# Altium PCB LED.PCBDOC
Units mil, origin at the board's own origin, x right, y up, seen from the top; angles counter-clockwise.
Board outline 6000 x 4000 mil, 2 copper layers (Top Layer, Bottom Layer); 19 components, 28 nets, 110 pads, 17 vias.
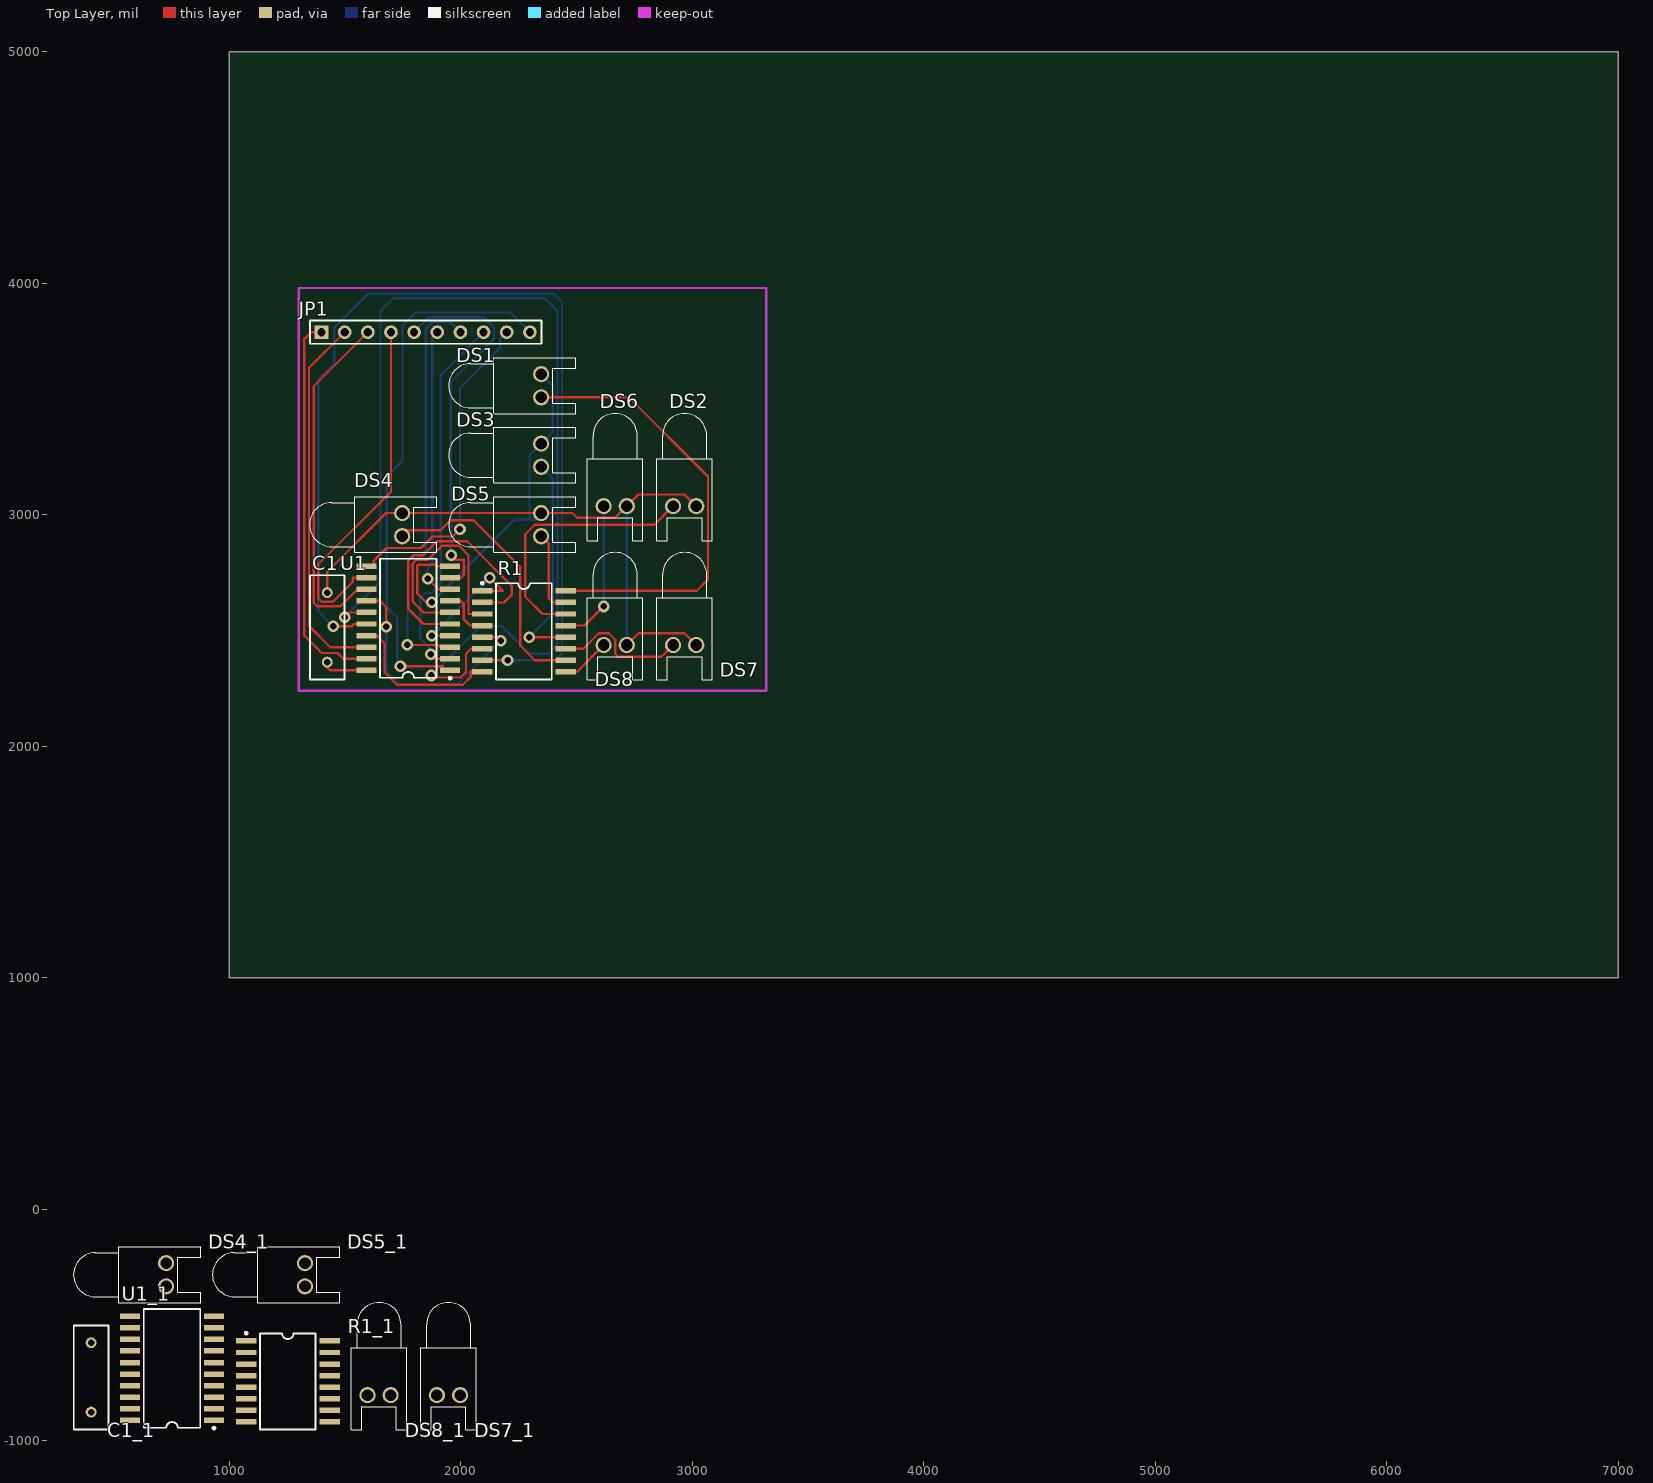
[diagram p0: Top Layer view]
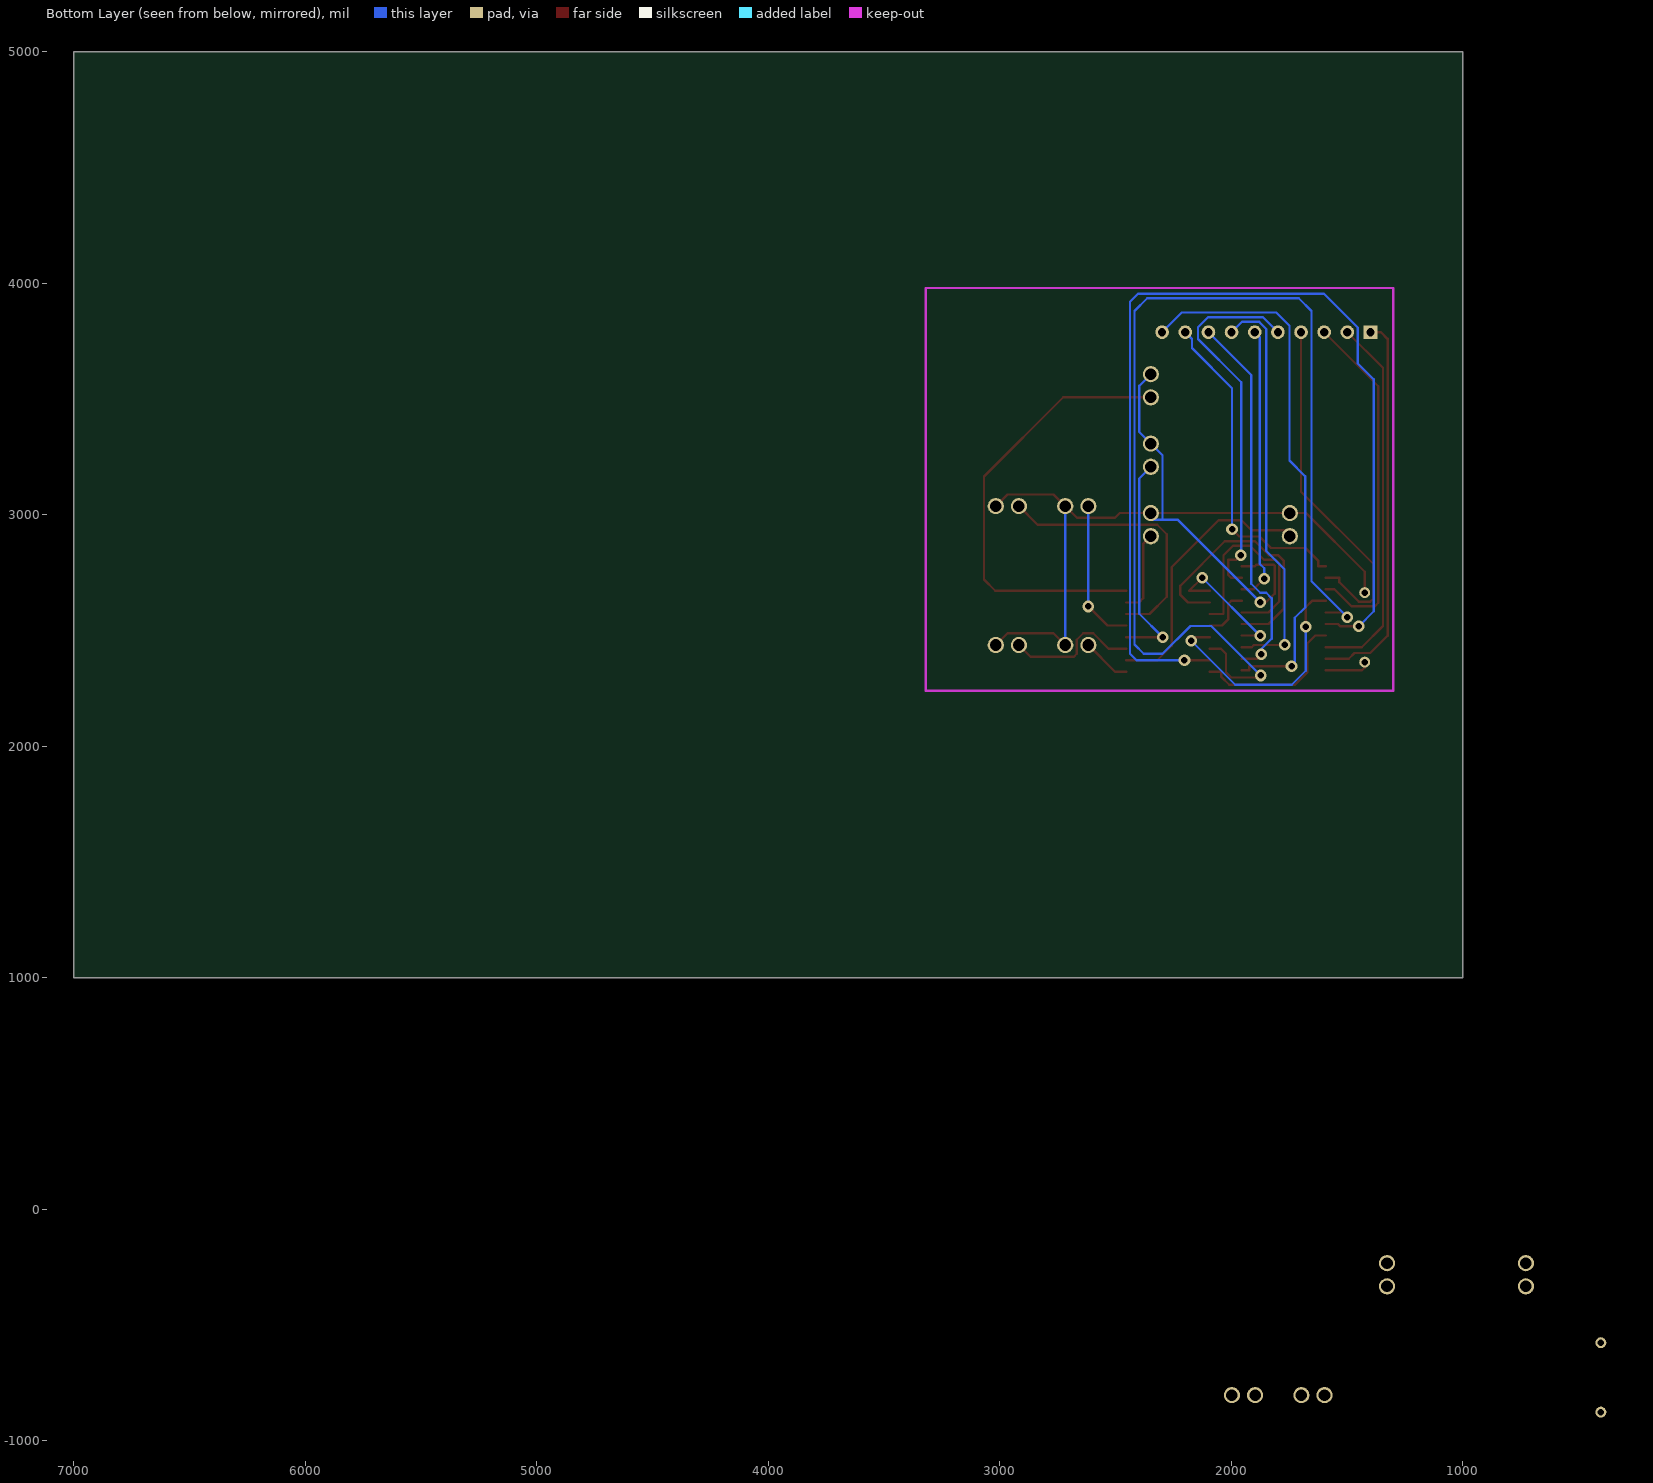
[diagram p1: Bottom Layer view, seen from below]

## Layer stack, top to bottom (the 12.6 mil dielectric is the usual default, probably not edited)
Top Layer: signal copper 1.4
Dielectric: dielectric 12.6, FR-4, Dk 4.8
Bottom Layer: signal copper 1.4

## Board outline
1000,1000 7000,1000 7000,5000 1000,5000

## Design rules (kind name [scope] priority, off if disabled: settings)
Clearance [All] p1: gap=10
ComponentClearance [All] p1: gap=10 collisioncheckmode=0
PolygonConnect [All] p1: connectstyle=Relief reliefconductorwidth=10 reliefentries=4 polygonreliefangle="90 Angle"
RoomDefinition LED [InComponentClass('LED')] p1: confinementstyle=ConfineIn formatcopy=TRUE outline 1320,2280 3220,2280 3220,3900 1320,3900
RoutingLayers [All] p1: top layer=Horizontal bottom layer=Vertical
RoutingVias [All] p1: holewidth=28 width=50 viastyle="Through Hole" minholewidth=28 minwidth=50 maxholewidth=28 maxwidth=50
SolderMaskExpansion [All] p1: expansion=4
TestPointUsage [All] p1: valid=0 allowmultiple=FALSE
Testpoint [All] p1: side=15 testpointundercomponent=TRUE minsize=40 maxsize=100 preferedsize=60 minholesize=0 maxholesize=40 preferedholesize=32 testpointgrid=1 style=1023 order=-539222988
Width [All] p1: maxlimit=10 minlimit=10 preferedwidth=10
16 further rules are at their usual default settings.

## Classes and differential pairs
component class LED: C1 DS1 DS2 DS3 DS4 DS5 DS6 DS7 DS8 JP1 R1 U1

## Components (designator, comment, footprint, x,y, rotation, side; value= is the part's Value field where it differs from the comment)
C1 "0.1uF" RAD-0.3 1423.94,2663.94 r270 top
C1_1 "0.1uF" RAD-0.3 403.94,-576.06 r270 top (schematic designator C1)
DS1 "LED0" LED-0 2347.5,3557.5 r270 top
DS2 "LED0" LED-0 2967.5,3037.5 r180 top
DS3 "LED0" LED-0 2347.5,3257.5 r270 top
DS4 "LED0" LED-0 1747.5,2957.5 r270 top
DS4_1 "LED0" LED-0 727.5,-282.5 r270 top (schematic designator DS4)
DS5 "LED0" LED-0 2347.5,2957.5 r270 top
DS5_1 "LED0" LED-0 1327.5,-282.5 r270 top (schematic designator DS5)
DS6 "LED0" LED-0 2667.5,3037.5 r180 top
DS7 "LED0" LED-0 2967.5,2437.5 r180 top
DS7_1 "LED0" LED-0 1947.5,-802.5 r180 top (schematic designator DS7)
DS8 "LED0" LED-0 2667.5,2437.5 r180 top
DS8_1 "LED0" LED-0 1647.5,-802.5 r180 top (schematic designator DS8)
JP1 "Header 10" HDR1X10 1398.94,3788.94 r0 top
R1 "330" SO-G16/G6.9 2273.41,2496.61 r270 top
R1_1 "330" SO-G16/G6.9 1253.41,-743.39 r270 top (schematic designator R1)
U1 "TPIC6B273DW" SO-G20 1773.41,2553.31 r90 top
U1_1 "TPIC6B273DW" SO-G20 753.41,-686.69 r90 top (schematic designator U1)

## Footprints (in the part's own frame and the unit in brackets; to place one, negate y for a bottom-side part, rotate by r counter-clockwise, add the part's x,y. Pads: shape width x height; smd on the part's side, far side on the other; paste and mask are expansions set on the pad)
HDR1X10 [mm]
  rect 1.5x1.5 hole 0.9: 1(0,0)
  round 1.5 hole 0.9: 2(2.54,0) 3(5.08,0) 4(7.62,0) 5(10.16,0) 6(12.7,0) 7(15.24,0) 8(17.78,0) 9(20.32,0) 10(22.86,0)
  silkscreen extent -1.27,-1.27 24.13,1.27
LED-0 [mil]
  round 70 hole 50: 1(50,0) 2(-50,0)
  silkscreen extent -120,-400 120,150
RAD-0.3 [mm]
  round 1.2 hole 0.7: 1(0,0) 2(7.62,0)
  silkscreen extent -1.91,-1.9 9.52,1.91
SO-G16/G6.9 [mm]
  rect 0.6x2.25 smd: 1(-4.445,-4.575) 2(-3.175,-4.575) 3(-1.905,-4.575) 4(-0.635,-4.575) 5(0.635,-4.575) 6(1.905,-4.575) 7(3.175,-4.575) 8(4.445,-4.575) 9(4.445,4.575) 10(3.175,4.575) 11(1.905,4.575) 12(0.635,4.575) 13(-0.635,4.575) 14(-1.905,4.575) 15(-3.175,4.575) 16(-4.445,4.575)
  silkscreen extent -5.42,-4.7 5.27,3.05
SO-G20 [mm]
  rect 0.6x2.2 smd: 1(-5.715,-4.6) 2(-4.445,-4.6) 3(-3.175,-4.6) 4(-1.905,-4.6) 5(-0.635,-4.6) 6(0.635,-4.6) 7(1.905,-4.6) 8(3.175,-4.6) 9(4.445,-4.6) 10(5.715,-4.6) 11(5.715,4.6) 12(4.445,4.6) 13(3.175,4.6) 14(1.905,4.6) 15(0.635,4.6) 16(-0.635,4.6) 17(-1.905,4.6) 18(-3.175,4.6) 19(-4.445,4.6) 20(-5.715,4.6)
  silkscreen extent -6.69,-4.73 6.53,3.1

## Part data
C1 C1_1: library part Cap, "Capacitor"
DS1 DS2 DS3 DS4 DS4_1 DS5 DS5_1 DS6 DS7 DS7_1 DS8 DS8_1: "Typical INFRARED GaAs LED"
JP1: "Header, 10-Pin"
R1 R1_1: library part "Res Pack3", "Resistor Array"
U1 U1_1: "Power Logic Octal D-Type Latch"

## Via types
v1: diameter 50, hole 28, Top Layer to Bottom Layer, 17 vias

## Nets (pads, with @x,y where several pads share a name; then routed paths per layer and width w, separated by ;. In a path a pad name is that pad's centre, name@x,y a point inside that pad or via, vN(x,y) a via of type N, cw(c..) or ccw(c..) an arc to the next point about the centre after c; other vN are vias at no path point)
GND: C1.1 DS1.2 DS2.2 DS3.2 DS4.2 DS5.2 DS6.2 DS7.2 DS8.2 U1.10 | length 4486.4
  Top Layer w10: C1.1 1423.94,2753.94 1677.5,3007.5 DS4.2 DS5.2 2482,3007.5 2502.5,2987 2667,2987 DS6.2 2768,3088 2967,3088 DS2.2 ; v1(1876,2623) 1849,2623 1813,2659 1813,2780 1817,2784 1892.31,2784 1898,2778.31 U1.10 ; DS8.2 2768,2488 2967,2488 DS7.2
  Bottom Layer w10: v1(1876,2623) 2231,2978 2297,2978 ; DS5.2 2347.5,2978 2297,2978 ; DS1.2 2398,3557 2398,3358 DS3.2 2297,3257 2297,2978 ; DS8.2 DS6.2
NetDS1_1: DS1.1 R1.16 | length 1942.5
  Top Layer w10: DS1.1 2726.5,3507.5 3068,3166 3068,2720 3019.61,2671.61 R1.16
NetDS2_1: DS2.1 R1.14 | length 1164.5
  Top Layer w10: R1.14 2353.39,2571.61 2279,2646 2279,2916.5 2320,2957.5 2837.5,2957.5 DS2.1
NetDS3_1: DS3.1 R1.12 | length 955.2
  Top Layer w10: v1(2297,2471.61) R1.12
  Bottom Layer w10: v1(2297,2471.61) 2398,2572.61 2398,3157 DS3.1
NetDS4_1: DS4.1 R1.10 | length 1199.9
  Top Layer w10: DS4.1 1747.5,2934 1914,2934 1957,2977 2054,2977 2257,2774 2257,2434.61 2320,2371.61 R1.10
NetDS5_1: DS5.1 R1.15 | length 361.5
  Top Layer w10: DS5.1 2381,2874 2381,2640 2399.39,2621.61 R1.15
NetDS6_1: DS6.1 R1.13 | length 631.5
  Top Layer w10: R1.13 2535,2521.61 v1(2617.5,2604.11)
  Bottom Layer w10: v1(2617.5,2604.11) DS6.1
NetDS7_1: DS7.1 R1.11 | length 590
  Top Layer w10: R1.11 2530,2421.61 2596.39,2488 2640,2488 2667.5,2460.5 2667.5,2399.5 2680,2387 2867,2387 DS7.1
NetDS8_1: DS8.1 R1.9 | length 212
  Top Layer w10: R1.9 2501.61,2321.61 DS8.1
NetJP1_1: JP1.1 U1.19 | length 1676.5
  Top Layer w10: JP1.1 1353.94,3788.94 1325,3760 1325,2478 1400,2403 1468.31,2403 1493,2378.31 U1.19
NetJP1_2: JP1.2 U1.18 | length 1618
  Top Layer w10: JP1.2 1345,3635 1345,2520 1436.69,2428.31 U1.18
NetJP1_3: JP1.3 U1.13 | length 1529.7
  Top Layer w10: U1.13 1554,2678.31 1480.69,2605 1380,2605 1365,2620 1365,3555 JP1.3
NetJP1_4: JP1.4 U1.12 | length 1546.4
  Top Layer w10: U1.12 1534,2728.31 1534,2709.32 1449.68,2625 1400,2625 1385,2640 1385,2786.06 1698.94,3100 JP1.4
NetJP1_5: JP1.5 U1.9 | length 1644
  Top Layer w10: U1.9 2001.13,2728.31 2013,2740.18 2013,2806 1979,2806 v1(1959,2826)
  Bottom Layer w10: JP1.5 1864,3854 2100,3854 2144,3810 2144,3760 1957,3573 1957,2828 v1(1959,2826)
NetJP1_6: JP1.6 U1.8 | length 1197.3
  Top Layer w10: v1(1858,2724) 1903.69,2678.31 U1.8
  Bottom Layer w10: v1(1858,2724) 1858,2769 1877,2788 1877,3767 JP1.6
NetJP1_7: JP1.7 U1.3 | length 1767.7
  Top Layer w10: v1(1770,2438) 1902.31,2438 1912,2428.31 U1.3
  Bottom Layer w10: v1(1770,2438) 1770,2765 1849,2844 1849,3803 1880,3834 1953.88,3834 JP1.7
NetJP1_8: JP1.8 U1.2 | length 1630.7
  Top Layer w10: v1(1870,2397) 1888.69,2378.31 U1.2
  Bottom Layer w10: v1(1870,2397) 1870,2421 1826,2465 1826,2640 1849,2663 1875,2663 1914,2702 1914,3604 JP1.8
NetJP1_9: JP1.9 U1.11 | length 1419.3
  Top Layer w10: U1.11 1624,2778.31 1624,2801 1680,2857 1829,2857 1878,2906 1966,2906 v1(1997,2937)
  Bottom Layer w10: v1(1997,2937) 1997,3547 2170,3720 2170,3760 JP1.9
NetJP1_10: JP1.10 U1.1 | length 2364.6
  Top Layer w10: v1(1740,2346) 1923,2346 1923,2328.31 U1.1
  Bottom Layer w10: v1(1740,2346) 1726,2360 1726,2555 1681,2600 1681,3166 1749,3234 1749,3817 1806,3874 2213.88,3874 JP1.10
NetR1_1: R1.1 U1.4 | length 600.9
  Top Layer w10: v1(1876,2478.31) U1.4 ; R1.1 2182.39,2671.61 v1(2125.85,2728.15)
  Bottom Layer w10: v1(1876,2478.31) v1(2125.85,2728.15)
NetR1_2: R1.2 U1.5 | length 1156.2
  Top Layer w10: U1.5 1840,2528.31 1773,2595.31 1773,2800 1799,2826 1838,2826 1898,2886 2028,2886 2220,2694 2220,2654 2187.61,2621.61 R1.2
NetR1_3: R1.3 U1.6 | length 947.8
  Top Layer w10: U1.6 1840,2578.31 1793,2625.31 1793,2790 1809,2806 1859,2806 1919,2866 1993,2866 2034,2825 2034,2571.61 R1.3
NetR1_4: R1.4 U1.7 | length 222
  Top Layer w10: U1.7 2000,2628.31 2014,2614.31 2014,2547.61 2040,2521.61 R1.4
NetR1_5: R1.5 U1.14 | length 1056.3
  Top Layer w10: U1.14 1651,2628.31 1679,2600.31 v1(1679,2516) ; R1.5 2157.39,2471.61 v1(2173,2456)
  Bottom Layer w10: v1(1679,2516) 1679,2326 1739,2266 1983,2266 v1(2173,2456)
NetR1_6: R1.6 U1.15 | length 4759.5
  Top Layer w10: v1(1499,2558.31) 1519,2578.31 U1.15 ; v1(1873,2306) 1882,2297 2000,2297 2023,2320 2023,2400 2044.61,2421.61 R1.6
  Bottom Layer w10: v1(1499,2558.31) 1654,2713.31 1654,3880 1709,3935 2363,3935 2418,3880 2418,2440 2378,2400 2297,2400 2177,2520 2087,2520 v1(1873,2306)
NetR1_7: R1.7 U1.16 | length 4428.5
  Top Layer w10: v1(1450,2518) 1528.69,2518 1539,2528.31 U1.16 ; R1.7 2202,2371.61 v1(2202.39,2372)
  Bottom Layer w10: v1(1450,2518) 1385,2583 1385,3585 1454,3654 1454,3809 1600,3955 2403,3955 2438,3920 2438,2400 2410,2372 v1(2202.39,2372)
NetR1_8: R1.8 U1.17 | length 697.8
  Top Layer w10: U1.17 1637.69,2478.31 1671,2445 1671,2320 1725,2266 2009,2266 2043,2300 2043,2321.61 R1.8
VCC: C1.2 U1.20 | length 197.2
  Top Layer w10: C1.2 1423.94,2340 1435.63,2328.31 U1.20
pads on no net: C1_1.1 C1_1.2 DS4_1.1 DS4_1.2 DS5_1.1 DS5_1.2 DS7_1.1 DS7_1.2 DS8_1.1 DS8_1.2 R1_1.1 R1_1.2 R1_1.3 R1_1.4 R1_1.5 R1_1.6 R1_1.7 R1_1.8 R1_1.9 R1_1.10 R1_1.11 R1_1.12 R1_1.13 R1_1.14 R1_1.15 R1_1.16 U1_1.1 U1_1.2 U1_1.3 U1_1.4 U1_1.5 U1_1.6 U1_1.7 U1_1.8 U1_1.9 U1_1.10 U1_1.11 U1_1.12 U1_1.13 U1_1.14 U1_1.15 U1_1.16 U1_1.17 U1_1.18 U1_1.19 U1_1.20

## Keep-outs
Keep-Out Layer:
  lines w10: 1300,2240 1300,3200 1300,3980 2340,3980 3320,3980 3320,2240 1300,2240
